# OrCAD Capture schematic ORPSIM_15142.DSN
size A
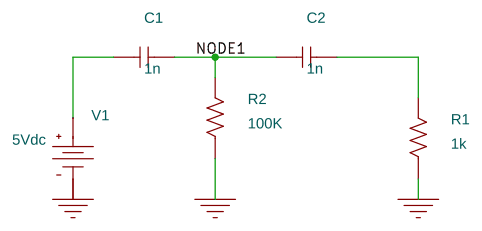
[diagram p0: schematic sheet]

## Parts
C1  1n  [CK05]
C2  1n  [CK05]
R1  1k  [RC05]
R2  100K  [RC05]
V1  VDC

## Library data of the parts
C1 C2 = C
R1 R2 = R
V1 = VDC: DC: 5Vdc

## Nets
0: R1.1 R2.1 V1.1(-)
NODE1: C1.2 C2.1 R2.2
N00118: C1.1 V1.0(+)
N00129: C2.2 R1.2
